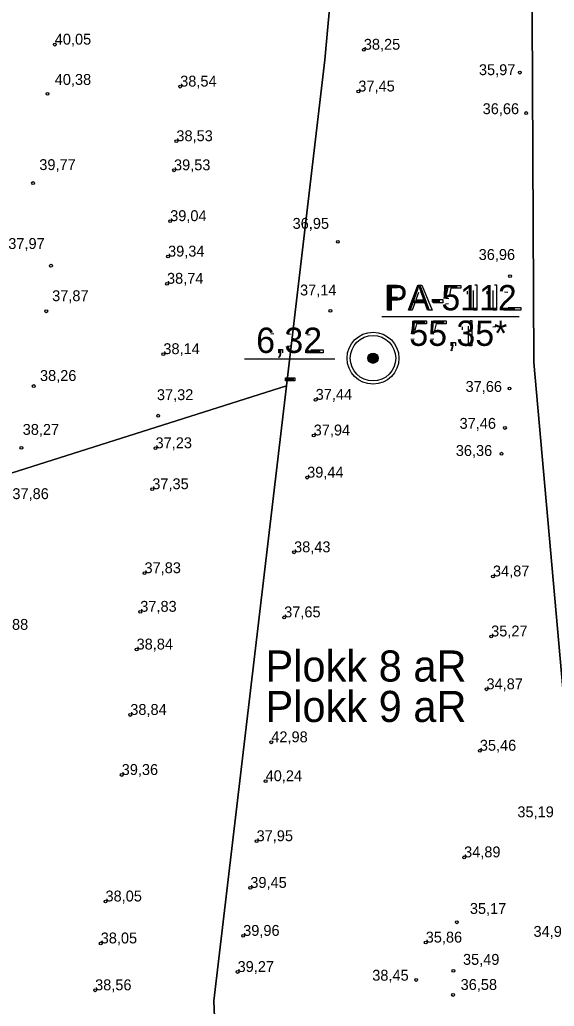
# Model space of a CAD drawing. Extents: x 700746 to 706058, y 6570320 to 6580460.
# Drawn here: x 703007.3 to 703127.7, y 6576090 to 6576312 of the extents above; entities that cross this region are included whole.
import ezdxf

# ---------------------------------------------------------------- set-up
doc = ezdxf.new("R2010")
doc.units = 0
for name, color, linetype in [('GEOLPUNKT', 7, 'Continuous'), ('KORGUS-EH2000', 7, 'Continuous'), ('Plokid', 7, 'Continuous'), ('VWX2_MV_PLOKK', 7, 'Continuous')]:
    doc.layers.add(name, color=color, linetype=linetype)

msp = doc.modelspace()

# ---------------------------------------------------------------- linework, layer by layer
at = {"layer": 'GEOLPUNKT'}
for p, q in [((703088.87, 6576245.23), (703119.78, 6576245.23)), ((703088.87, 6576245.23), (703119.78, 6576245.23)), ((703057.93, 6576235.69), (703078.24, 6576235.69)), ((703057.93, 6576235.69), (703078.24, 6576235.69))]:
    msp.add_line(p, q, dxfattribs=at)
for points in [[(703090.15, 6576246.63), (703090.15, 6576252.33), (703092.3, 6576252.33)], [(703092.37, 6576251.66), (703090.91, 6576251.66), (703090.91, 6576249.62)], [(703094.84, 6576246.63), (703097.03, 6576252.33), (703097.85, 6576252.33), (703100.18, 6576246.63), (703099.32, 6576246.63), (703098.66, 6576248.35), (703096.27, 6576248.35), (703095.64, 6576246.63), (703094.84, 6576246.63)], [(703103.93, 6576249.24), (703103.27, 6576249.33), (703103.82, 6576252.25), (703106.66, 6576252.25), (703106.66, 6576251.59), (703104.38, 6576251.59), (703104.08, 6576250.06)], [(703109.76, 6576252.35), (703110.21, 6576252.35), (703110.21, 6576246.63)], [(703114.18, 6576252.35), (703114.63, 6576252.35), (703114.63, 6576246.63)], [(703090.91, 6576249.62), (703092.38, 6576249.62)], [(703097.12, 6576250.64), (703096.49, 6576248.97)], [(703096.49, 6576248.97), (703098.42, 6576248.97), (703097.82, 6576250.55)], [(703108.11, 6576250.24), (703108.11, 6576250.92)], [(703110.21, 6576246.63), (703109.51, 6576246.63), (703109.51, 6576251.09)], [(703112.53, 6576250.24), (703112.53, 6576250.92)], [(703114.63, 6576246.63), (703113.93, 6576246.63), (703113.93, 6576251.09)], [(703117.19, 6576250.63), (703116.47, 6576250.7)], [(703092.37, 6576248.94), (703090.91, 6576248.94), (703090.91, 6576246.63), (703090.15, 6576246.63)], [(703100.41, 6576248.34), (703100.41, 6576249.04), (703102.57, 6576249.04), (703102.57, 6576248.34), (703100.41, 6576248.34)], [(703103.15, 6576248.12), (703103.88, 6576248.18)], [(703120.1, 6576247.3), (703120.1, 6576246.63), (703116.34, 6576246.63)], [(703117.31, 6576247.3), (703120.1, 6576247.3)], [(703096.15, 6576241.24), (703095.5, 6576241.33), (703096.05, 6576244.25), (703098.88, 6576244.25), (703098.88, 6576243.59), (703096.61, 6576243.59), (703096.3, 6576242.06)], [(703100.58, 6576241.24), (703099.92, 6576241.33), (703100.48, 6576244.25), (703103.31, 6576244.25), (703103.31, 6576243.59), (703101.04, 6576243.59), (703100.73, 6576242.06)], [(703106.97, 6576242.24), (703106.97, 6576242.92)], [(703109.07, 6576238.63), (703108.37, 6576238.63), (703108.37, 6576243.09)], [(703108.62, 6576244.35), (703109.07, 6576244.35), (703109.07, 6576238.63)], [(703114.5, 6576242.93), (703113.81, 6576242.87)], [(703064.51, 6576241.34), (703063.82, 6576241.28)], [(703068.29, 6576241.16), (703067.59, 6576241.28)], [(703068.9, 6576239.74), (703068.98, 6576240.35)], [(703072.7, 6576241.04), (703071.98, 6576241.11)], [(703067.52, 6576238.55), (703068.22, 6576238.64)], [(703095.37, 6576240.12), (703096.11, 6576240.18)], [(703099.8, 6576240.12), (703100.53, 6576240.18)], [(703104.6, 6576238.63), (703104.6, 6576239.42), (703105.4, 6576239.42), (703105.4, 6576238.63)], [(703105, 6576238.63), (703104.6, 6576238.63)], [(703065.83, 6576235.91), (703065.63, 6576236.21)], [(703065.68, 6576237.04), (703065.68, 6576237.83), (703066.48, 6576237.83), (703066.48, 6576237.04)], [(703066.08, 6576237.04), (703065.68, 6576237.04)], [(703075.62, 6576237.71), (703075.62, 6576237.04), (703071.85, 6576237.04)], [(703072.82, 6576237.71), (703075.62, 6576237.71)], [(703104.75, 6576237.5), (703104.56, 6576237.8)], [(703067.13, 6576230.75), (703067.13, 6576231.45), (703069.28, 6576231.45), (703069.28, 6576230.75), (703067.13, 6576230.75)]]:
    msp.add_lwpolyline(points, dxfattribs=at)
for radius in [5.84, 5.12, 1.15, 1.02, 0.896, 0.768, 0.64, 0.512, 0.384, 0.256, 0.128]:
    msp.add_circle((703086.85, 6576235.85), radius, dxfattribs=at)
at = {"layer": 'KORGUS-EH2000'}
for centre in [(703015.2, 6576306.43), (703084.78, 6576305.28), (703119.92, 6576300.14), (703043.44, 6576296.99), (703083.55, 6576295.88), (703013.58, 6576295.37), (703121.34, 6576291.03), (703042.58, 6576284.7), (703042.05, 6576278.15), (703010.31, 6576275.28), (703041.18, 6576266.71), (703078.92, 6576262.05), (703040.71, 6576258.73), (703014.35, 6576256.67), (703117.7, 6576254.32), (703040.47, 6576252.61), (703013.29, 6576246.42), (703077.25, 6576246.5), (703039.65, 6576236.77), (703010.46, 6576229.59), (703117.58, 6576229.02), (703073.94, 6576226.49), (703038.49, 6576222.92), (703116.56, 6576220.15), (703073.5, 6576218.47), (703007.69, 6576215.69), (703037.89, 6576215.59), (703115.79, 6576214.35), (703072.02, 6576208.97), (703037.16, 6576206.37), (703069.08, 6576192.17), (703035.4, 6576187.47), (703113.86, 6576186.74), (703034.45, 6576178.78), (703066.85, 6576177.53), (703113.45, 6576173.23), (703033.62, 6576170.29), (703112.4, 6576161.33), (703032.2, 6576155.57), (703063.95, 6576149.41), (703110.9, 6576147.51), (703030.27, 6576142.05), (703062.67, 6576140.65), (703060.64, 6576127.15), (703107.36, 6576123.51), (703059.23, 6576116.64), (703026.62, 6576113.58), (703105.74, 6576108.9), (703057.62, 6576105.84), (703025.54, 6576104.14), (703098.72, 6576104.33), (703104.94, 6576097.98), (703056.36, 6576097.71), (703096.58, 6576095.91), (703024.28, 6576093.6), (703104.88, 6576092.54)]:
    msp.add_circle(centre, 0.32, dxfattribs=at)
at = {"layer": 'Plokid'}
msp.add_line((702842.72, 6576158.42), (703067.36, 6576229.67), dxfattribs=at)
for points in [[(703290.64, 6576959.22), (703356.01, 6576531.94), (703307.59, 6576229.01), (703289.69, 6575965.85), (703290.02, 6575933.75), (703291.51, 6575829.64), (703294.32, 6575609.52), (703294.77, 6575576.79), (703154.76, 6575556.6), (703019.06, 6575536.97), (703053.36, 6575698.14), (703145.59, 6575981.92), (703123.04, 6576234.88), (703120.61, 6576749.6), (703011.59, 6576989.47), (702968.34, 6577084.63), (702917.3, 6577059.88)], [(703072.3, 6576854.63), (703101.31, 6576579.97), (703076.01, 6576303.02), (703067.36, 6576229.67), (703051.03, 6576091.21), (703059.38, 6575886.59), (702981.97, 6575701.33), (702866.03, 6575711.28), (702865.95, 6575985.44), (702842.72, 6576158.42), (702849.09, 6576223.53)]]:
    msp.add_lwpolyline(points, dxfattribs=at)
at = {"layer": 'VWX2_MV_PLOKK'}
for points in [[(703044.07, 6577449.05), (703125.37, 6577441.7), (703167.08, 6577172.26), (703170.22, 6577152.1), (703231.53, 6577106.55), (703277.36, 6577072.83), (703360.09, 6576531.99), (703311.6, 6576228.52), (703293.62, 6575965.66), (703294.04, 6575933.77), (703295.43, 6575829.7), (703298.36, 6575609.6), (703298.84, 6575573.29), (703155.29, 6575552.59), (703145.59, 6575981.92), (703123.04, 6576234.88), (703120.61, 6576749.6), (703011.59, 6576989.47), (703015.74, 6577110.88), (702996.73, 6577210.32)], [(702840.26, 6576874.26), (702915.96, 6576894.45), (703039.76, 6576927.49), (703072.13, 6576856.26), (703101.31, 6576579.97), (703076.01, 6576303.02), (703067.36, 6576229.67), (702842.72, 6576158.42), (702853.4, 6576267.5), (702860.12, 6576517.75), (702877.29, 6576548.25), (702900.72, 6576571.25)], [(702840.26, 6576874.26), (702915.96, 6576894.45), (703039.76, 6576927.49), (703072.13, 6576856.26), (703101.31, 6576579.97), (703076.01, 6576303.02), (703067.36, 6576229.67), (702842.72, 6576158.42), (702853.4, 6576267.5), (702860.12, 6576517.75), (702877.29, 6576548.25), (702900.72, 6576571.25)], [(703145.59, 6575981.92), (703053.36, 6575698.14), (703018.17, 6575532.81), (702852.27, 6575508.89), (702837.26, 6575620.73), (702848.38, 6575976.59), (702782.85, 6576063.35), (702782.57, 6576096.37), (702842.53, 6576210.56), (702853.4, 6576267.5), (702842.72, 6576158.42), (702865.95, 6575985.44), (702867.94, 6575888.34), (702866.03, 6575711.28), (702981.97, 6575701.33), (703059.38, 6575886.59), (703051.03, 6576091.21), (703067.36, 6576229.67), (703076.01, 6576303.02), (703101.31, 6576579.97), (703072.3, 6576854.63), (703072.13, 6576856.26), (703120.61, 6576749.6), (703123.04, 6576234.88)], [(703145.59, 6575981.92), (703053.36, 6575698.14), (703018.17, 6575532.81), (702852.27, 6575508.89), (702837.26, 6575620.73), (702848.38, 6575976.59), (702782.85, 6576063.35), (702782.57, 6576096.37), (702842.53, 6576210.56), (702853.4, 6576267.5), (702842.72, 6576158.42), (702865.95, 6575985.44), (702867.94, 6575888.34), (702866.03, 6575711.28), (702981.97, 6575701.33), (703059.38, 6575886.59), (703051.03, 6576091.21), (703067.36, 6576229.67), (703076.01, 6576303.02), (703101.31, 6576579.97), (703072.3, 6576854.63), (703072.13, 6576856.26), (703120.61, 6576749.6), (703123.04, 6576234.88)]]:
    msp.add_lwpolyline(points, close=True, dxfattribs=at)
msp.add_lwpolyline([(703187.67, 6576999.67), (703190.39, 6576656.32), (703340.88, 6576657.54), (703360.09, 6576531.99), (703311.6, 6576228.52), (703293.62, 6575965.66), (703294.04, 6575933.77), (703295.43, 6575829.7), (703298.36, 6575609.6), (703298.84, 6575573.29), (703155.29, 6575552.59), (703018.17, 6575532.81), (703053.36, 6575698.14), (703145.59, 6575981.92), (703123.04, 6576234.88), (703120.61, 6576749.6), (703011.59, 6576989.47)], dxfattribs=at)
msp.add_lwpolyline([(703187.67, 6576999.67), (703190.39, 6576656.32), (703340.88, 6576657.54), (703360.09, 6576531.99), (703311.6, 6576228.52), (703293.62, 6575965.66), (703294.04, 6575933.77), (703295.43, 6575829.7), (703298.36, 6575609.6), (703298.84, 6575573.29), (703155.29, 6575552.59), (703018.17, 6575532.81), (703053.36, 6575698.14), (703145.59, 6575981.92), (703123.04, 6576234.88), (703120.61, 6576749.6), (703011.59, 6576989.47)], dxfattribs=at)

# ---------------------------------------------------------------- texts
at = {"layer": 'GEOLPUNKT'}
for s, p in [('PA-5112', (703089.54, 6576246.63)), ('6,32', (703060.55, 6576237.04)), ('55,35*', (703095.04, 6576238.63)), ('-', (703066.88, 6576229.04))]:
    msp.add_text(s, height=5.7, dxfattribs=at).set_placement(p)
at = {"layer": 'KORGUS-EH2000'}
for s, p in [('40,05 ', (703015.2, 6576306.43)), ('38,25 ', (703084.78, 6576305.28)), ('35,97 ', (703110.7, 6576299.56)), ('40,38 ', (703015.19, 6576297.37)), ('38,54 ', (703043.44, 6576296.99)), ('37,45 ', (703083.55, 6576295.88)), ('36,66 ', (703111.54, 6576290.78)), ('38,53 ', (703042.58, 6576284.7)), ('39,77 ', (703011.72, 6576278.2)), ('39,53 ', (703042.05, 6576278.15)), ('39,04 ', (703041.18, 6576266.71)), ('36,95 ', (703068.75, 6576264.97)), ('37,97 ', (703004.73, 6576260.44)), ('39,34 ', (703040.71, 6576258.73)), ('36,96 ', (703110.64, 6576257.97)), ('38,74 ', (703040.47, 6576252.61)), ('37,14 ', (703070.42, 6576249.98)), ('37,87 ', (703014.61, 6576248.69)), ('38,14 ', (703039.65, 6576236.77)), ('38,26 ', (703011.87, 6576230.73)), ('37,66 ', (703107.69, 6576228.27)), ('37,32 ', (703038.2, 6576226.42)), ('37,44 ', (703073.94, 6576226.49)), ('37,46 ', (703106.34, 6576219.96)), ('38,27 ', (703007.98, 6576218.6)), ('37,94 ', (703073.5, 6576218.47)), ('37,23 ', (703037.89, 6576215.59)), ('36,36 ', (703105.49, 6576213.85)), ('39,44 ', (703072.02, 6576208.97)), ('37,35 ', (703037.16, 6576206.37)), ('37,86 ', (703005.66, 6576204.14)), ('38,43 ', (703069.08, 6576192.17)), ('37,83 ', (703035.4, 6576187.47)), ('34,87 ', (703113.86, 6576186.74)), ('37,83 ', (703034.45, 6576178.78)), ('37,65 ', (703066.85, 6576177.53)), ('38,88 ', (703001.02, 6576174.72)), ('35,27 ', (703113.45, 6576173.23)), ('38,84 ', (703033.62, 6576170.29)), ('34,87 ', (703112.4, 6576161.33)), ('38,84 ', (703032.2, 6576155.57)), ('42,98 ', (703063.95, 6576149.41)), ('35,46 ', (703110.9, 6576147.51)), ('39,36 ', (703030.27, 6576142.05)), ('40,24 ', (703062.67, 6576140.65)), ('35,19 ', (703119.36, 6576132.53)), ('37,95 ', (703060.64, 6576127.15)), ('34,89 ', (703107.36, 6576123.51)), ('39,45 ', (703059.23, 6576116.64)), ('38,05 ', (703026.62, 6576113.58)), ('35,17 ', (703108.66, 6576110.78)), ('39,96 ', (703057.62, 6576105.84)), ('34,92 ', (703122.99, 6576105.62)), ('38,05 ', (703025.54, 6576104.14)), ('35,86 ', (703098.72, 6576104.33)), ('35,49 ', (703107.11, 6576099.32)), ('39,27 ', (703056.36, 6576097.71)), ('38,45 ', (703086.68, 6576095.75)), ('38,56 ', (703024.28, 6576093.6)), ('36,58 ', (703106.58, 6576093.67))]:
    msp.add_text(s, height=2.45, dxfattribs=at).set_placement(p)
at = {"layer": 'Plokid'}
for s, p in [('Plokk 8 aR', (703062.64, 6576163.08)), ('Plokk 9 aR', (703062.64, 6576153.98))]:
    msp.add_text(s, height=7, dxfattribs=at).set_placement(p)

doc.saveas('drawing.dxf')
